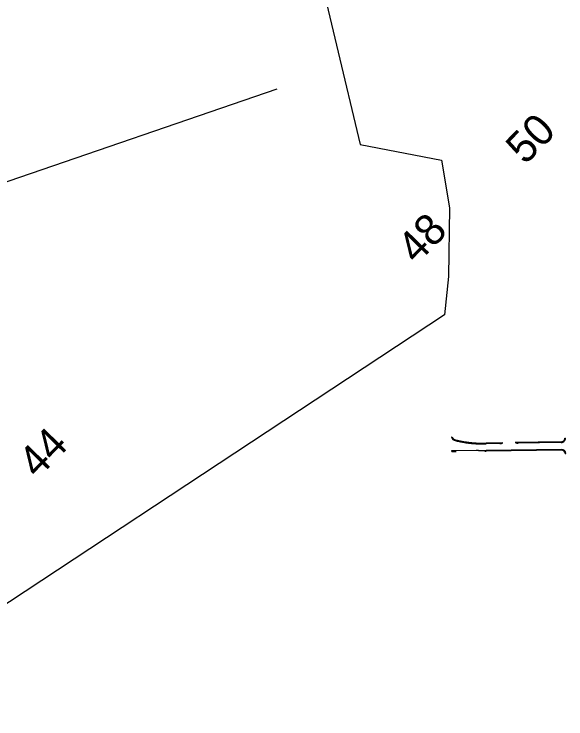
# Model space of a CAD drawing. Extents: x -5665 to 1997148, y 4 to 812485.
# Drawn here: x 1965773 to 1969323, y 797997 to 802527 of the extents above; entities that cross this region are included whole.
import ezdxf

# ---------------------------------------------------------------- set-up
doc = ezdxf.new("R2010")
doc.units = 0
for name, color, linetype in [('RD_HC_CL_Rel', 7, 'Continuous'), ('RD_PD_SW', 7, 'Continuous'), ('RD_SHT_ShtClip', 7, 'Continuous'), ('RD_SHT_TX', 7, 'Continuous')]:
    doc.layers.add(name, color=color, linetype=linetype)

msp = doc.modelspace()

# ---------------------------------------------------------------- linework, layer by layer
at = {"layer": 'RD_HC_CL_Rel'}
msp.add_line((1965223.3, 801278), (1967465.8, 802047.7), dxfattribs=at)
at = {"layer": 'RD_PD_SW'}
for p, q in [((1968586.3, 799807.6), (1968590.5, 799809.4)), ((1969316.3, 799801.6), (1969320.8, 799801.7)), ((1968918, 799771.4), (1968809.3, 799769.7)), ((1968897.8, 799766.6), (1968809.5, 799765.2)), ((1969293.2, 799777.2), (1968997.5, 799772.6)), ((1969293.3, 799772.7), (1969016.7, 799768.4)), ((1968589.8, 799721.7), (1968746.7, 799724.2)), ((1968590.1, 799715.7), (1968589.8, 799721.7)), ((1968590.1, 799715.7), (1968616.9, 799716.2)), ((1969295, 799728.8), (1968810.2, 799721.2)), ((1969295, 799724.3), (1968810.2, 799716.7)), ((1969318.9, 799702.5), (1969323.3, 799702.8))]:
    msp.add_line(p, q, dxfattribs=at)
for points in [[(1968635.5, 799780.3), (1968635.5, 799780.3), (1968635.5, 799780.3)], [(1968636.4, 799784.7), (1968636.4, 799784.7), (1968636.4, 799784.7)], [(1968693.1, 799770.5), (1968693.1, 799770.5), (1968693.1, 799770.5)], [(1968693.7, 799775), (1968693.7, 799775), (1968693.7, 799775)], [(1968751.2, 799765.5), (1968751.2, 799765.5), (1968751.2, 799765.5)], [(1968751.4, 799770), (1968751.4, 799770), (1968751.4, 799770)]]:
    msp.add_lwpolyline(points, dxfattribs=at)
for centre, radius, start, end in [((1968621.2, 799822.6), 38, 203.2444, 256.8509), ((1968621.2, 799822.6), 33.5, 203.2444, 256.1951), ((1969292.8, 799800.7), 23.5, 270.8885, 2.0353), ((1969292.8, 799800.7), 28, 270.8885, 2.0353), ((1968897, 799814.6), 48, 270.8885, 295.8963), ((1969016, 799811.4), 43, 244.4418, 270.8885), ((1969295.4, 799700.8), 28, 4.1634, 90.8885), ((1969295.4, 799700.8), 23.5, 4.1634, 90.8885)]:
    msp.add_arc(centre, radius, start, end, dxfattribs=at)
for points in [[(1968612.6, 799785.6), (1968613.4, 799785.4), (1968614.2, 799785.2), (1968616, 799784.7), (1968617, 799784.5), (1968618.9, 799784), (1968619.9, 799783.8), (1968621.9, 799783.4), (1968626.7, 799782.2), (1968631.6, 799781.2), (1968635.5, 799780.3)], [(1968613.2, 799790), (1968613.7, 799789.9), (1968614.2, 799789.8), (1968615.2, 799789.6), (1968615.6, 799789.5), (1968617.1, 799789.1), (1968620, 799788.4), (1968626.7, 799786.8), (1968632.5, 799785.6), (1968636.4, 799784.7)], [(1968635.5, 799780.3), (1968636.1, 799780.2), (1968636.7, 799780.1), (1968637.9, 799779.8), (1968639.6, 799779.5), (1968643.8, 799778.6), (1968652.2, 799777), (1968664.2, 799774.8), (1968676.2, 799772.9), (1968684.6, 799771.7), (1968688.9, 799771.1), (1968690.7, 799770.9), (1968691.9, 799770.7), (1968692.5, 799770.6), (1968693.1, 799770.5)], [(1968636.4, 799784.7), (1968637, 799784.6), (1968637.6, 799784.5), (1968638.8, 799784.2), (1968640.5, 799783.9), (1968644.7, 799783), (1968653, 799781.4), (1968664.9, 799779.2), (1968676.9, 799777.3), (1968685.3, 799776.1), (1968689.5, 799775.6), (1968691.3, 799775.3), (1968692.5, 799775.2), (1968693.1, 799775.1), (1968693.7, 799775)], [(1968693.1, 799770.5), (1968693.7, 799770.5), (1968694.3, 799770.4), (1968695.5, 799770.2), (1968697.3, 799770), (1968701.5, 799769.5), (1968710, 799768.6), (1968722.1, 799767.4), (1968734.2, 799766.5), (1968742.7, 799765.9), (1968747, 799765.7), (1968748.8, 799765.6), (1968750, 799765.6), (1968750.6, 799765.5), (1968751.2, 799765.5)], [(1968693.7, 799775), (1968694.3, 799774.9), (1968694.9, 799774.9), (1968696.1, 799774.7), (1968697.9, 799774.5), (1968702.1, 799774), (1968710.5, 799773), (1968722.5, 799771.9), (1968734.5, 799770.9), (1968743, 799770.4), (1968747.2, 799770.2), (1968749, 799770.1), (1968750.2, 799770.1), (1968750.8, 799770), (1968751.4, 799770)], [(1968751.2, 799765.5), (1968751.8, 799765.5), (1968752.4, 799765.5), (1968753.6, 799765.4), (1968755.5, 799765.3), (1968759.7, 799765.2), (1968768.2, 799764.9), (1968780.3, 799764.7), (1968792.5, 799764.8), (1968801, 799765), (1968804.6, 799765.1), (1968806.4, 799765.1), (1968807, 799765.1), (1968808.3, 799765.2), (1968808.9, 799765.2), (1968809.5, 799765.2)], [(1968751.4, 799770), (1968752, 799770), (1968752.6, 799770), (1968753.8, 799769.9), (1968755.6, 799769.8), (1968759.9, 799769.7), (1968768.3, 799769.4), (1968780.4, 799769.2), (1968792.4, 799769.3), (1968800.9, 799769.5), (1968804.5, 799769.6), (1968806.9, 799769.6), (1968808.1, 799769.7), (1968809.3, 799769.7)]]:
    msp.add_open_spline(points, degree=3, dxfattribs=at)
for points in [[(1968746.7, 799724.2), (1968746.8, 799724.1), (1968747.6, 799724.1), (1968748.5, 799724)], [(1968748.5, 799724), (1968749.3, 799723.9), (1968750.1, 799723.9), (1968751, 799723.8), (1968751.8, 799723.7), (1968752.6, 799723.7), (1968753.5, 799723.6), (1968754.3, 799723.5), (1968755.1, 799723.5), (1968756, 799723.4), (1968756.8, 799723.3), (1968757.6, 799723.3), (1968758.4, 799723.2), (1968759.3, 799723.2), (1968760.1, 799723.1), (1968760.9, 799723), (1968761.8, 799723), (1968762.6, 799722.9), (1968763.4, 799722.9), (1968764.3, 799722.8), (1968765.1, 799722.8), (1968765.9, 799722.7), (1968766.8, 799722.7), (1968767.6, 799722.6), (1968768.4, 799722.6), (1968769.3, 799722.5), (1968770.1, 799722.5), (1968770.9, 799722.4), (1968771.8, 799722.4), (1968772.6, 799722.3), (1968773.4, 799722.3), (1968774.3, 799722.2), (1968775.1, 799722.2), (1968775.9, 799722.1), (1968776.8, 799722.1), (1968777.6, 799722.1), (1968778.4, 799722), (1968779.3, 799722), (1968780.1, 799722), (1968780.9, 799721.9), (1968781.8, 799721.9), (1968782.6, 799721.8), (1968783.4, 799721.8), (1968784.3, 799721.8), (1968785.1, 799721.8), (1968785.9, 799721.7), (1968786.8, 799721.7), (1968787.6, 799721.7), (1968788.4, 799721.6), (1968789.3, 799721.6), (1968790.1, 799721.6), (1968790.9, 799721.6), (1968791.8, 799721.5), (1968792.6, 799721.5), (1968793.5, 799721.5), (1968794.3, 799721.5), (1968795.1, 799721.4), (1968796, 799721.4), (1968796.8, 799721.4), (1968797.6, 799721.4), (1968798.5, 799721.4), (1968799.3, 799721.4), (1968800.1, 799721.3), (1968801, 799721.3), (1968801.8, 799721.3), (1968802.6, 799721.3), (1968803.5, 799721.3), (1968804.3, 799721.3), (1968805.1, 799721.3), (1968806, 799721.3), (1968806.8, 799721.3), (1968807.6, 799721.3), (1968808.5, 799721.2), (1968810.2, 799721.2)], [(1968801.8, 799716.8), (1968802.6, 799716.8), (1968803.4, 799716.8), (1968804.3, 799716.8), (1968805.1, 799716.8), (1968805.9, 799716.8), (1968806.8, 799716.8), (1968807.6, 799716.8), (1968808.5, 799716.7), (1968810.1, 799716.7)]]:
    msp.add_spline(points, degree=3, dxfattribs=at)
at = {"layer": 'RD_SHT_ShtClip'}
msp.add_lwpolyline([(1962404, 800141.4), (1962156.8, 800249.1), (1961619.9, 801061.9), (1967047, 804639.1), (1967746.1, 803578.5), (1967695.1, 802969), (1968000.2, 801689.9), (1968522.9, 801587.9), (1968575.1, 801281.2), (1968568.4, 800839.6), (1968542.7, 800594.7), (1964601.3, 797996.7), (1963740.9, 798826.2)], close=True, dxfattribs=at)

# ---------------------------------------------------------------- texts
at = {"layer": 'RD_SHT_TX'}
for s, p in [('50', (1969061.2, 801553.4)), ('48', (1968362.5, 800913.4)), ('44', (1965923.7, 799535.2))]:
    msp.add_text(s, height=200, rotation=45.6376, dxfattribs=at).set_placement(p)

doc.saveas('drawing.dxf')
